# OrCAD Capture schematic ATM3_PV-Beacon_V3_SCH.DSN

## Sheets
1 Config: title: ATM3202 PV Beacon Demo; rev: 3.0; note: ATM3221-KYB-02-RB
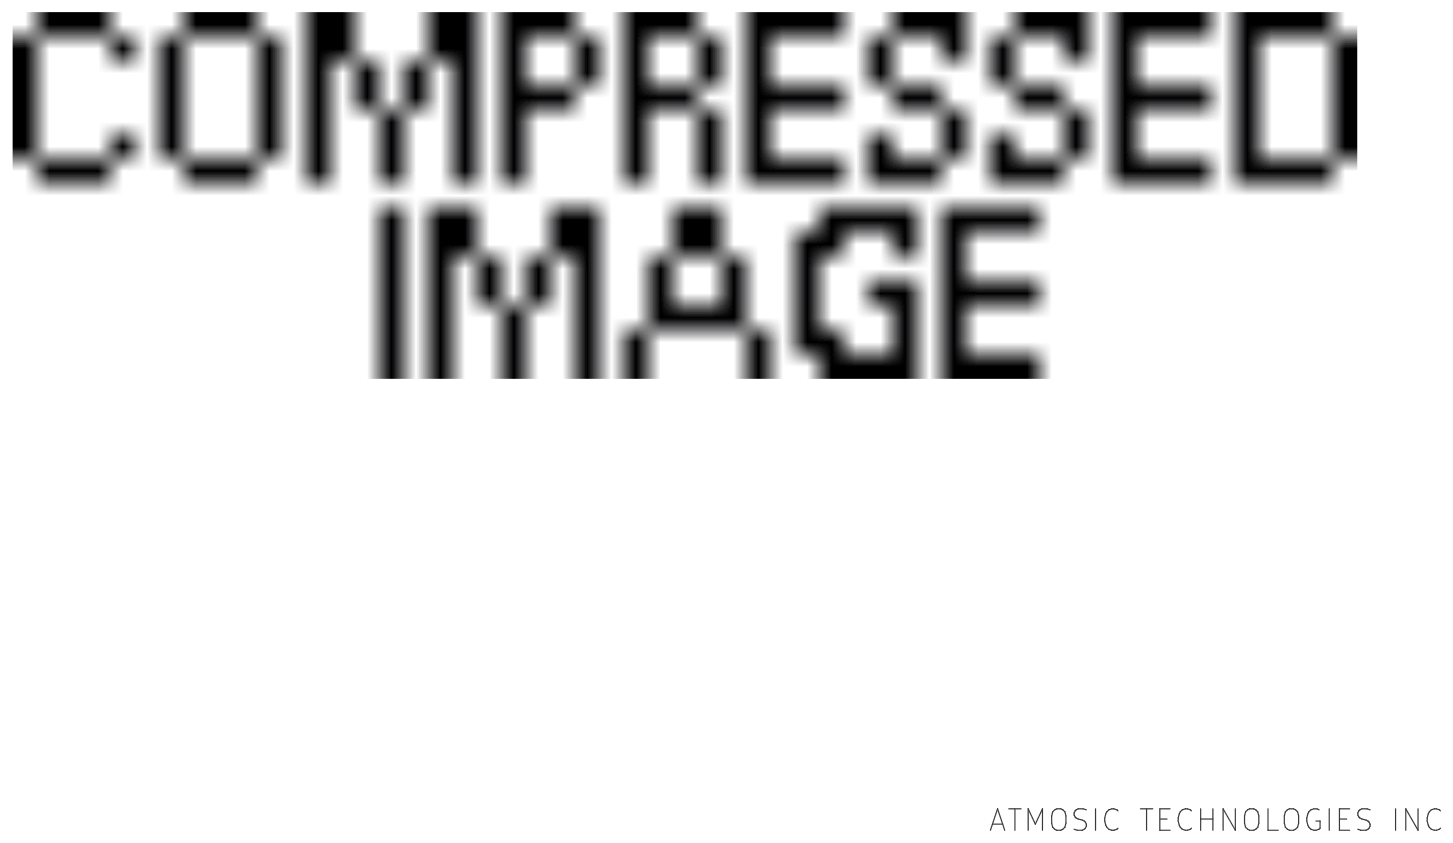
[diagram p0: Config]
2 Schematic: size A
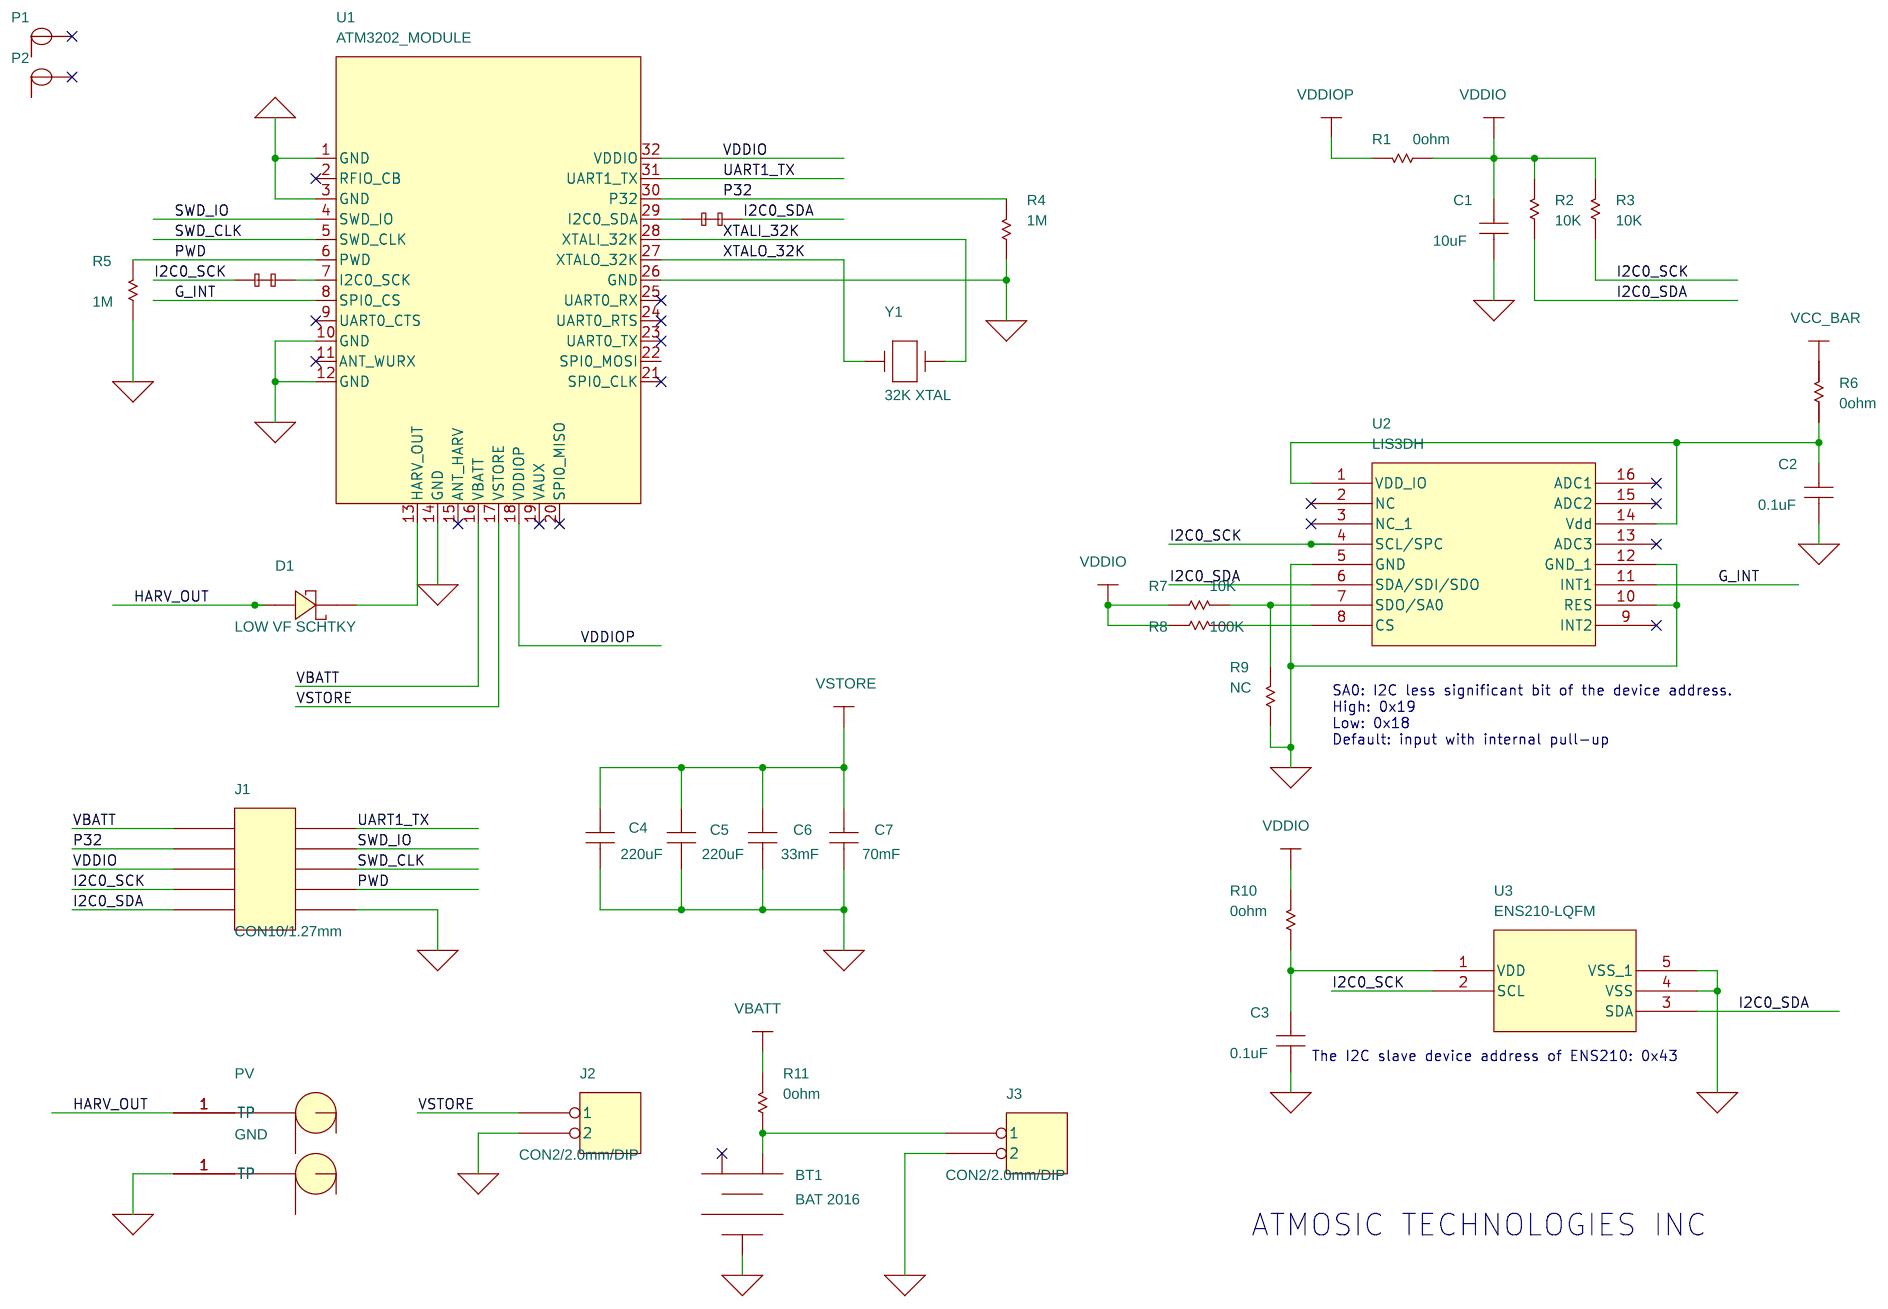
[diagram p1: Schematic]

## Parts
BT1  BAT 2016  [3012TR]
C1  10uF  [0402_ATM]
C2  0.1uF  [0402_ATM]
C3  0.1uF  [0402_ATM]
C4  220uF  [1206]
C5  220uF  [1206]
C6  33mF  [SUPERCAP_33MF]
C7  70mF  [SUPERCAP_70MF]
D1  LOW VF SCHTKY  [0402]
GND  TP  [PAD100]
J1  CON10/1.27mm  [CON_5X2_50MIL_SMD]
J2  CON2/2.0mm/DIP  [CON2/2.0mm/DIP]
J3  CON2/2.0mm/DIP  [CON2/2.0mm/DIP]
P1  TP  [PLACINGHOLE]
P2  TP  [PLACINGHOLE]
PV  TP  [PAD100]
R1  0ohm  [0402_ATM]
R2  10K  [0402_ATM]
R3  10K  [0402_ATM]
R4  1M  [0402_ATM]
R5  1M  [0402_ATM]
R6  0ohm  [0402_ATM]
R7  10K  [0402_ATM]
R8  100K  [0402_ATM]
R9  NC  [0402_ATM]
R10  0ohm  [0402_ATM]
R11  0ohm  [0402_ATM]
U1  ATM3202_MODULE  [M3_MINI_MODULE_V1_FP_E]
U2  LIS3DH  [LIS3DH_STD]
U3  ENS210-LQFM  [ENS210-LQFM]
U4  0201_DUMMY  [0201_DUMMY]
U5  0201_DUMMY  [0201_DUMMY]
Y1  32K XTAL  [XTAL-SMD2-2.0X1.2MM]

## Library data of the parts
BT1 = BAT_1
C1-C7 = SMALL_CAP
D1 = DIODE_SCHOTTKY
GND PV = TP
J1 = CON8_1
J2 = HEADER_2
J3 = HEADER_2_1
P1 P2 = TP_0
R1-R11 = SMALL_R1
U1 = ATM2202_Module_0
U2 = LIS3DHTR_0
U3 = ENS210-LQFM_2
U4 U5 = 0201_DUMMY_2
Y1 = XTAL

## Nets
GND_SIGNAL: BT1.3(NEG) C1.2 C2.2 C3.2 C4.2 C5.2 C6.2 C7.2 GND.1(TP) J1.10 J2.2 J3.2 R4.1 R5.1 R9.1 U1.1(GND) U1.3(GND) U1.10(GND) U1.12(GND) U1.14(GND) U1.26(GND) U2.5(GND) U2.10(RES) U2.12(GND_1) U3.4(VSS) U3.5(VSS_1)
VBATT: J1.1 R11.2 U1.16(VBATT)
VDDIO: C1.1 J1.5 R1.1 R2.2 R3.2 R6.2 R7.1 R8.1 R10.2 U1.32(VDDIO)
VDDIOP: R1.2 U1.18(VDDIOP)
G_INT: U1.8(SPI0_CS) U2.11(INT1)
HARV_OUT: D1.1(ANODE) PV.1(TP)
I2C0_SCK: J1.7 R3.1 U2.4(SCL/SPC) U3.2(SCL) U4.2
I2C0_SDA: J1.9 R2.1 U2.6(SDA/SDI/SDO) U3.3(SDA) U5.1
P32: J1.3 R4.2 U1.30(P32)
PWD: J1.8 R5.2 U1.6(PWD)
SWD_CLK: J1.6 U1.5(SWD_CLK)
SWD_IO: J1.4 U1.4(SWD_IO)
UART1_TX: J1.2 U1.31(UART1_TX)
VSTORE: C4.1 C5.1 C6.1 C7.1 J2.1 U1.17(VSTORE)
XTALI_32K: U1.28(XTALI_32K) Y1.1
XTALO_32K: U1.27(XTALO_32K) Y1.2
N16088358: D1.2(CATHODE) U1.13(HARV_OUT)
N16112910: C2.1 R6.1 U2.1(VDD_IO) U2.14(Vdd)
N16113116: R8.2 U2.8(CS)
N16113725: C3.1 R10.1 U3.1(VDD)
N16117849: BT1.1(POS) J3.1 R11.1
N16131116: R7.2 R9.2 U2.7(SDO/SA0)
N16149756: U1.7(I2C0_SCK) U4.1
N16149839: U1.29(I2C0_SDA) U5.2

Not connected (* = marked no-connect by the designer): BT1 2(POS)*; P1 1(TP)*; P2 1(TP)*; U1 2(RFIO_CB)* 9(UART0_CTS)* 11(ANT_WURX)* 15(ANT_HARV)* 19(VAUX)* 20(SPI0_MISO)* 21(SPI0_CLK)* 22(SPI0_MOSI) 23(UART0_TX)* 24(UART0_RTS)* 25(UART0_RX)*; U2 2(NC)* 3(NC_1)* 9(INT2)* 13(ADC3)* 15(ADC2)* 16(ADC1)*

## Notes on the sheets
sheet 1
- ATMOSIC TECHNOLOGIES INC
sheet 2
- SA0: I2C less significant bit of the device address.
  High: 0x19
  Low: 0x18
  Default: input with internal pull-up
- The I2C slave device address of ENS210: 0x43
- ATMOSIC TECHNOLOGIES INC
